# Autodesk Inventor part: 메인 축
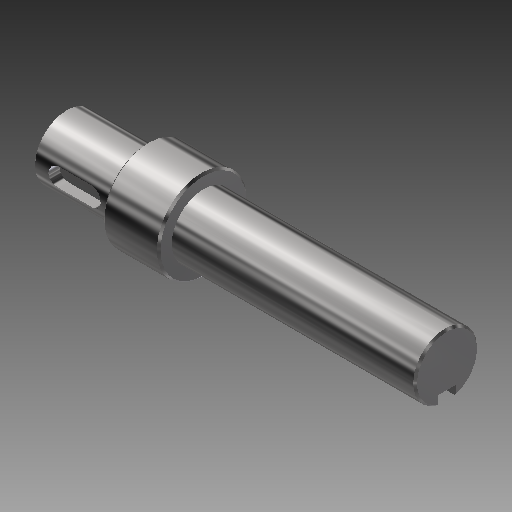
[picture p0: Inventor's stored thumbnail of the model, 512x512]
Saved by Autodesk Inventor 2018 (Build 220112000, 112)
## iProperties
Created: 2016-04
Part Number: 메인 축
Document SubType Name: Modeling
Designer: mdu
Density: 7.86 g/cm^3
Mass: 230.24 g
Surface Area: 74.3518 cm^2
Volume: 29.2926 cm^3
Material: 강철, 연강
Appearance: 반광택
Author: mdu
Revision Number: 1
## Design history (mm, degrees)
sketch "스케치1"
  geometry: L1 (10.497, -57.5)-(112.497, -57.5); L2 (10.497, -66)-(32.497, -66); L3 (32.497, -69.5)-(46.5, -69.5); L4 (46.5, -66)-(112.497, -66); L5 (112.497, -66)-(112.497, -57.5); L6 (10.497, -66)-(10.497, -57.5); L7 (46.5, -69.749)-(46.5, -45.251) reference; L8 (46.5, -69.5)-(46.5, -66); L9 (32.497, -69.5)-(32.497, -66); L10 (32.497, -35)-(32.497, -80) reference; 3 further points
  constraints: 16 end point, 3 point on line, 2 parallel, 2 perpendicular, 1 collinear, 1 horizontal, 1 midpoint
  dimensions: "d0" = 17 diameter of L4 L1; "d1" = 24 diameter of L3 L1; "d2" = 22 distance of L2.start L2.end; "d3" = 65.99692 distance of L4.start L4.end (derived); "d5" = 17 diameter of L2 L1; "d19" = 80 distance between parallel lines of L5 L9
revolve "회전1" sketch "스케치1" stored, may be unused: angle "d4" = 90 deg
feature "면 이동1"
chamfer "모따기1" distance "d6" = 0.5; stored, may be unused: second distance "d7" = 2, angle "d8" = 45 deg
node "작업 평면1"
sketch "스케치2"
  geometry: L1 (-11, -8)-(-11, 8) reference; L2 (-4.5, 2.5)-(4.5, 2.5); L3 (4.5, -2.5)-(-4.5, -2.5); A1 r 2.5 centre (4.5, 0) between (4.5, -2.5) and (4.5, 2.5); A2 r 2.5 centre (-4.5, 0) between (-4.5, 2.5) and (-4.5, -2.5); 2 further points
  constraints: 4 end point, 4 point on circle, 4 tangent, 2 centre point, 1 horizontal alignment, 1 midpoint, 1 parallel, 1 perpendicular
  dimensions: "d9" = 5 distance between parallel lines of L3 L2; "d10" = 14 dimension on A1 A2; "d11" = 4 distance edge to line of A2 L1
extrude "돌출1" cut sketch "스케치2" distance "d12" = 3; taper "d13" = 0 deg
node "작업 평면2"
sketch "스케치3"
  geometry: L1 (32.998, 8)-(32.998, -8) reference; L2 (32.998, 2.5)-(17.498, 2.5); L3 (17.498, -2.5)-(32.998, -2.5); A1 r 2.5 centre (17.498, 0) between (17.498, 2.5) and (17.498, -2.5); 2 further points
  constraints: 4 end point, 2 perpendicular, 2 point on circle, 2 point on line, 2 tangent, 1 centre point, 1 horizontal alignment, 1 midpoint
  dimensions: "d14" = 5 distance between parallel lines of L3 L2; "d15" = 18 dimension on A1 L1
extrude "돌출2" cut sketch "스케치3" distance "d16" = 3; taper "d17" = 0 deg
node "솔리드1"
node "참조4"
node "참조5"
